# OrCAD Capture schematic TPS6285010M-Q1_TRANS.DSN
size E; title: TPS6285010M-Q1 2.7-V to 6-V Step-Down Converter; rev: 1.0; note: Datasheet: SLUSDM0          EVM: SLVUBU8; note: Synchronous Step Down Converter; note: in SOT583 Package
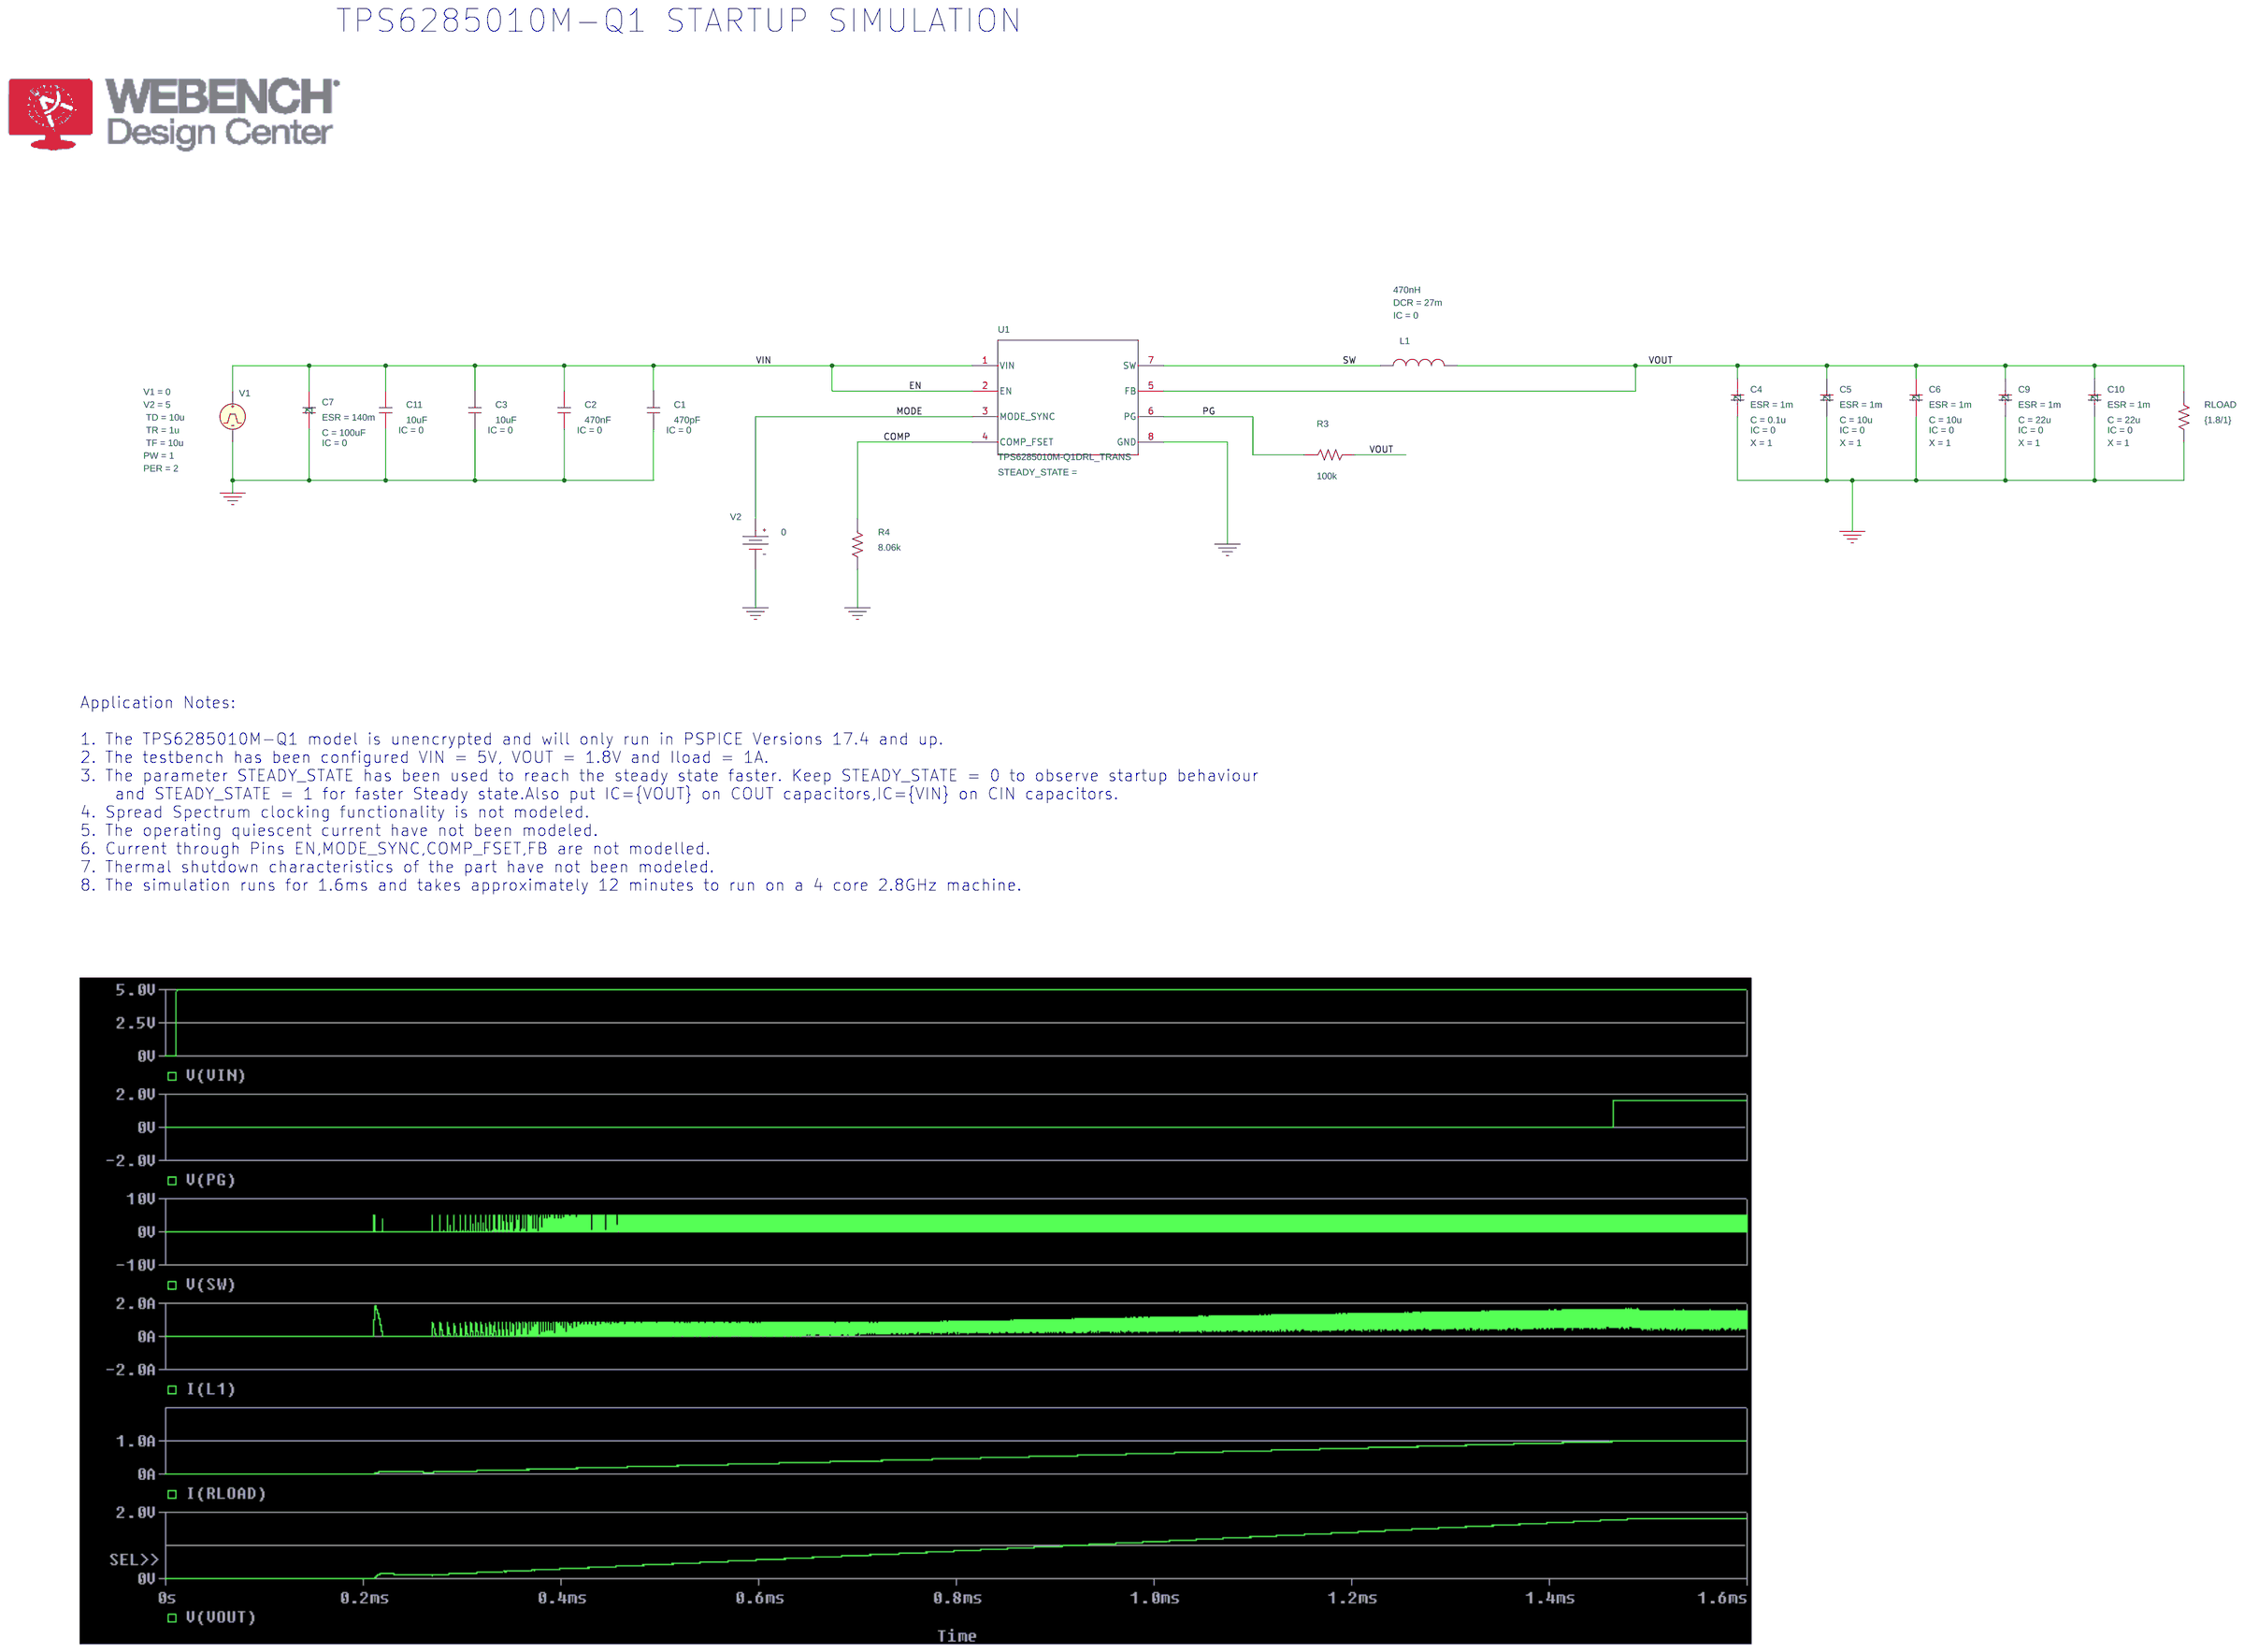
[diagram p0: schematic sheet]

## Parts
C1  470pF  [RAD/CK05]
C2  470nF  [RAD/CK05]
C3  10uF  [RAD/CK05]
C4  CESR
C5  CESR
C6  CESR
C7  CESR
C9  CESR
C10  CESR
C11  10uF  [RAD/CK05]
L1  470nH  [DISC/.350x.175/LS.200x.100/.034]
R3  100k  [AX/RC05]
R4  8.06k  [AX/RC05]
RLOAD  {1.8/1}  [AX/RC05]
U1  TPS6285010M-Q1DRL_TRANS  [DRL0008A-MFG]
V1  VPULSE
V2  VDC

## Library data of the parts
C1-C3 C11 = C: IC: 0
C4 = CESR_1_2: C: 0.1u; ESR: 1m; IC: 0; PSpiceTemplate: X^@REFDES %1 %2 @MODEL PARAMS: ?C|C=@C||C=10U| ?ESR|ESR=@ESR||ESR=2M| ?IC|IC=@IC||IC=0| ?X|X=@X||X=0|; X: 1
C5 = CESR_1_1: C: 10u; ESR: 1m; IC: 0; PSpiceTemplate: X^@REFDES %1 %2 @MODEL PARAMS: ?C|C=@C||C=10U| ?ESR|ESR=@ESR||ESR=2M| ?IC|IC=@IC||IC=0| ?X|X=@X||X=0|; X: 1
C6 = CESR_1: C: 10u; ESR: 1m; IC: 0; PSpiceTemplate: X^@REFDES %1 %2 @MODEL PARAMS: ?C|C=@C||C=10U| ?ESR|ESR=@ESR||ESR=2M| ?IC|IC=@IC||IC=0| ?X|X=@X||X=0|; X: 1
C7 = CESR_1_3: C: 100uF; ESR: 140m; IC: 0; PSpiceTemplate: X^@REFDES %1 %2 @MODEL PARAMS: ?C|C=@C||C=10U| ?ESR|ESR=@ESR||ESR=2M| ?IC|IC=@IC||IC=0| ?X|X=@X||X=0|; X: 1
C9 = CESR_1_5: C: 22u; ESR: 1m; IC: 0; PSpiceTemplate: X^@REFDES %1 %2 @MODEL PARAMS: ?C|C=@C||C=10U| ?ESR|ESR=@ESR||ESR=2M| ?IC|IC=@IC||IC=0| ?X|X=@X||X=0|; X: 1
C10 = CESR_1_4: C: 22u; ESR: 1m; IC: 0; PSpiceTemplate: X^@REFDES %1 %2 @MODEL PARAMS: ?C|C=@C||C=10U| ?ESR|ESR=@ESR||ESR=2M| ?IC|IC=@IC||IC=0| ?X|X=@X||X=0|; X: 1
L1 = L: DCR: 27m; IC: 0
R3 R4 RLOAD = R
U1 = TPS6285010M-Q1DRL_TRANS
V1 = VPULSE: PER: 2; PW: 1; TD: 10u; TF: 10u; TR: 1u; V1: 0; V2: 5
V2 = VDC: DC: 0

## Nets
0: C1.2 C2.2 C3.2 C4.2 C5.2 C6.2 C7.2 C9.2 C10.2 C11.2 R4.2 RLOAD.2 U1.8(GND) V1.2(-) V2.1(-)
COMP: R4.1 U1.4(COMP_FSET)
EN: C1.1 C2.1 C3.1 C7.1 C11.1 U1.1(VIN) U1.2(EN) V1.1(+)
MODE: U1.3(MODE_SYNC) V2.0(+)
PG: R3.1 U1.6(PG)
SW: L1.1 U1.7(SW)
VOUT: C4.1 C5.1 C6.1 C9.1 C10.1 L1.2 R3.2 RLOAD.1 U1.5(FB)

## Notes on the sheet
- TPS6285010M-Q1 STARTUP SIMULATION
- Application Notes:
  1. The TPS6285010M-Q1 model is unencrypted and will only run in PSPICE Versions 17.4 and up.
  2. The testbench has been configured VIN = 5V, VOUT = 1.8V and Iload = 1A.
  3. The parameter STEADY_STATE has been used to reach the steady state faster. Keep STEADY_STATE = 0 to observe startup behaviour
      and STEADY_STATE = 1 for faster Steady state.Also put IC={VOUT} on COUT capacitors,IC={VIN} on CIN capacitors.
  4. Spread Spectrum clocking functionality is not modeled.
  5. The operating quiescent current have not been modeled.
  6. Current through Pins EN,MODE_SYNC,COMP_FSET,FB are not modelled.
  7. Thermal shutdown characteristics of the part have not been modeled.
  8. The simulation runs for 1.6ms and takes approximately 12 minutes to run on a 4 core 2.8GHz machine.
